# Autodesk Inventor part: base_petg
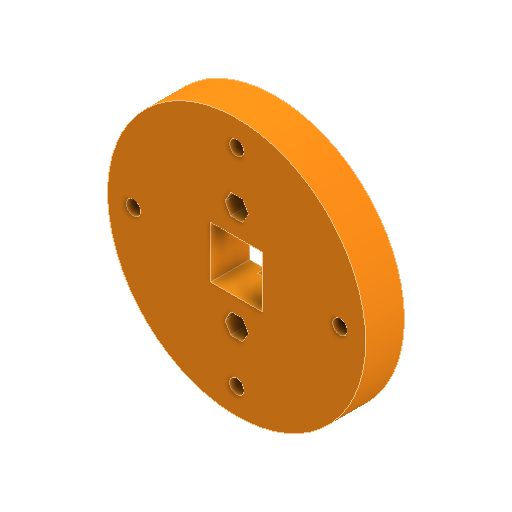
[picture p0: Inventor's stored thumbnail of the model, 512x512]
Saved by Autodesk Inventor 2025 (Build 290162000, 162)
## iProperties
Created: 2025-09
Part Number: base_petg
Material: Plastica PET
Document SubType Name: Modeling
Designer: Ryzen5700u
Density: 1.541 g/cm^3
Appearance: Arancione
Author: Ryzen5700u
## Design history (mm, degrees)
sketch "Schizzo1"
  geometry: C1 r 50 at (0, 0); 1 further point
  constraints: 1 centre point, 1 coincident
  dimensions: "d0" = 100 diameter of C1
extrude "Estrusione1" new body sketch "Schizzo1" distance "d1" = 15; taper "d2" = 0 deg
sketch "Schizzo2"
  geometry: 2 further points
  dimensions: "d3" = 40 distance of point (0, 0) point (0, 40)
hole "Foro1" sketch "Schizzo2" at (0, 40) diameter "d4" = 5.5; stored, may be unused: countersink angle "d8" = 90 deg, drill point angle "d10" = 118 deg; dims "d5" = 6, "d6" = 9, "d7" = 4, "d9" = 8
pattern_circular "Serie circolare1" dims angle "d12" = 360 deg
sketch "Schizzo3"
  geometry: L1 (1.8, -17)-(-1.8, -17) reference; L2 (-1.8, 17)-(1.8, 17) reference; L3 (0, 17)-(0, 20); L4 (0, -17)-(0, -20); 3 further points
  constraints: 4 end point, 2 coincident, 2 point on line, 1 perpendicular, 1 vertical
  dimensions: "d14" = 3 distance of L3.start L3.end; "d15" = 3 distance of L4.start L4.end
hole "Foro2" sketch "Schizzo3" at (0, -20), (0, 20) diameter "d16" = 4.5; stored, may be unused: countersink angle "d20" = 90 deg, drill point angle "d22" = 118 deg; dims "d17" = 6, "d18" = 10, "d19" = 5.7, "d21" = 8
sketch "Schizzo4"
  geometry: L1 (-4.5, -20)-(-2.25, -16.103); L2 (-2.25, -16.103)-(2.25, -16.103); L3 (2.25, -16.103)-(4.5, -20); L4 (4.5, -20)-(2.25, -23.897); L5 (2.25, -23.897)-(-2.25, -23.897); L6 (-2.25, -23.897)-(-4.5, -20); L7 (-4.5, 20)-(-2.25, 23.897); L8 (-2.25, 23.897)-(2.25, 23.897); L9 (2.25, 23.897)-(4.5, 20); L10 (4.5, 20)-(2.25, 16.103); L11 (2.25, 16.103)-(-2.25, 16.103); L12 (-2.25, 16.103)-(-4.5, 20); C1 r 2.25 at (0, -20) reference; C2 r 2.25 at (0, 20) reference; 3 further points
  constraints: 24 end point, 2 coincident, 26 other
  dimensions: "d23" = 4.5 distance of L1.end L2.end; "d24" = 4.5 distance of L10.end L11.end
extrude "Estrusione2" cut sketch "Schizzo4" distance "d25" = 7; taper "d26" = 0 deg
sketch "Schizzo5"
  geometry: L1 (10, 10)-(-10, 10); L2 (-10, 10)-(-10, -10); L3 (-10, -10)-(10, -10); L4 (10, -10)-(10, 10); L5 (10, 10)-(-10, -10); L6 (-10, 10)-(10, -10); 1 further point
  constraints: 12 end point, 2 midpoint, 2 parallel, 1 horizontal, 1 perpendicular
  dimensions: "d27" = 20 distance of L3.end L2.end; "d28" = 20 distance of L2.end L1.end
extrude "Estrusione3" cut sketch "Schizzo5" extent not by distance; stored distance "d29" = 0; taper "d30" = 0 deg
sketch "Schizzo6"
  geometry: L1 (0, -2.586)-(0, -42.708); L2 (-4, -10)-(4, -10); L3 (4, -10)-(4, -28); L4 (4, -28)-(-4, -28); L5 (-4, -28)-(-4, -10); L6 (10, -10)-(-10, -10) reference; 2 further points
  constraints: 10 end point, 3 perpendicular, 2 midpoint, 1 other
  dimensions: "d33" = 8 distance of L3.end L4.end; "d34" = 18 distance of L2.end L3.end
extrude "Estrusione4" cut sketch "Schizzo6" distance "d31" = 3; taper "d32" = 0 deg
mirror "Speculare1"
node "Solido1"
node "Riferimento1"
node "Riferimento2"
